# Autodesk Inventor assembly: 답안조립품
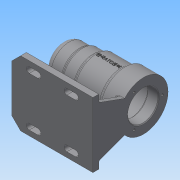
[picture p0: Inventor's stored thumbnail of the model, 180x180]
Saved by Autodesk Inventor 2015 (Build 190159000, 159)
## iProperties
Created: 2017-09
Part Number: 답안조립품
Document SubType Name: Assembly
Designer: owner
Author: owner
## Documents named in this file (2)
- C:\Users\owner\Desktop\470907V1002\답안조립품.iam
- C:\Users\owner\Desktop\470907V1002\본체.ipt
